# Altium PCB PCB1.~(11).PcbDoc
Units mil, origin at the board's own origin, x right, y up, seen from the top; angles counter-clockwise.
Board outline 2756 x 2756 mil, 4 copper layers (Top Layer, Internal Plane 1, Internal Plane 2, Bottom Layer), stack 18.2 mil thick; 11 components, 12 nets, 54 pads, 0 vias.
Unrouted connection lines stored in the file: 1.
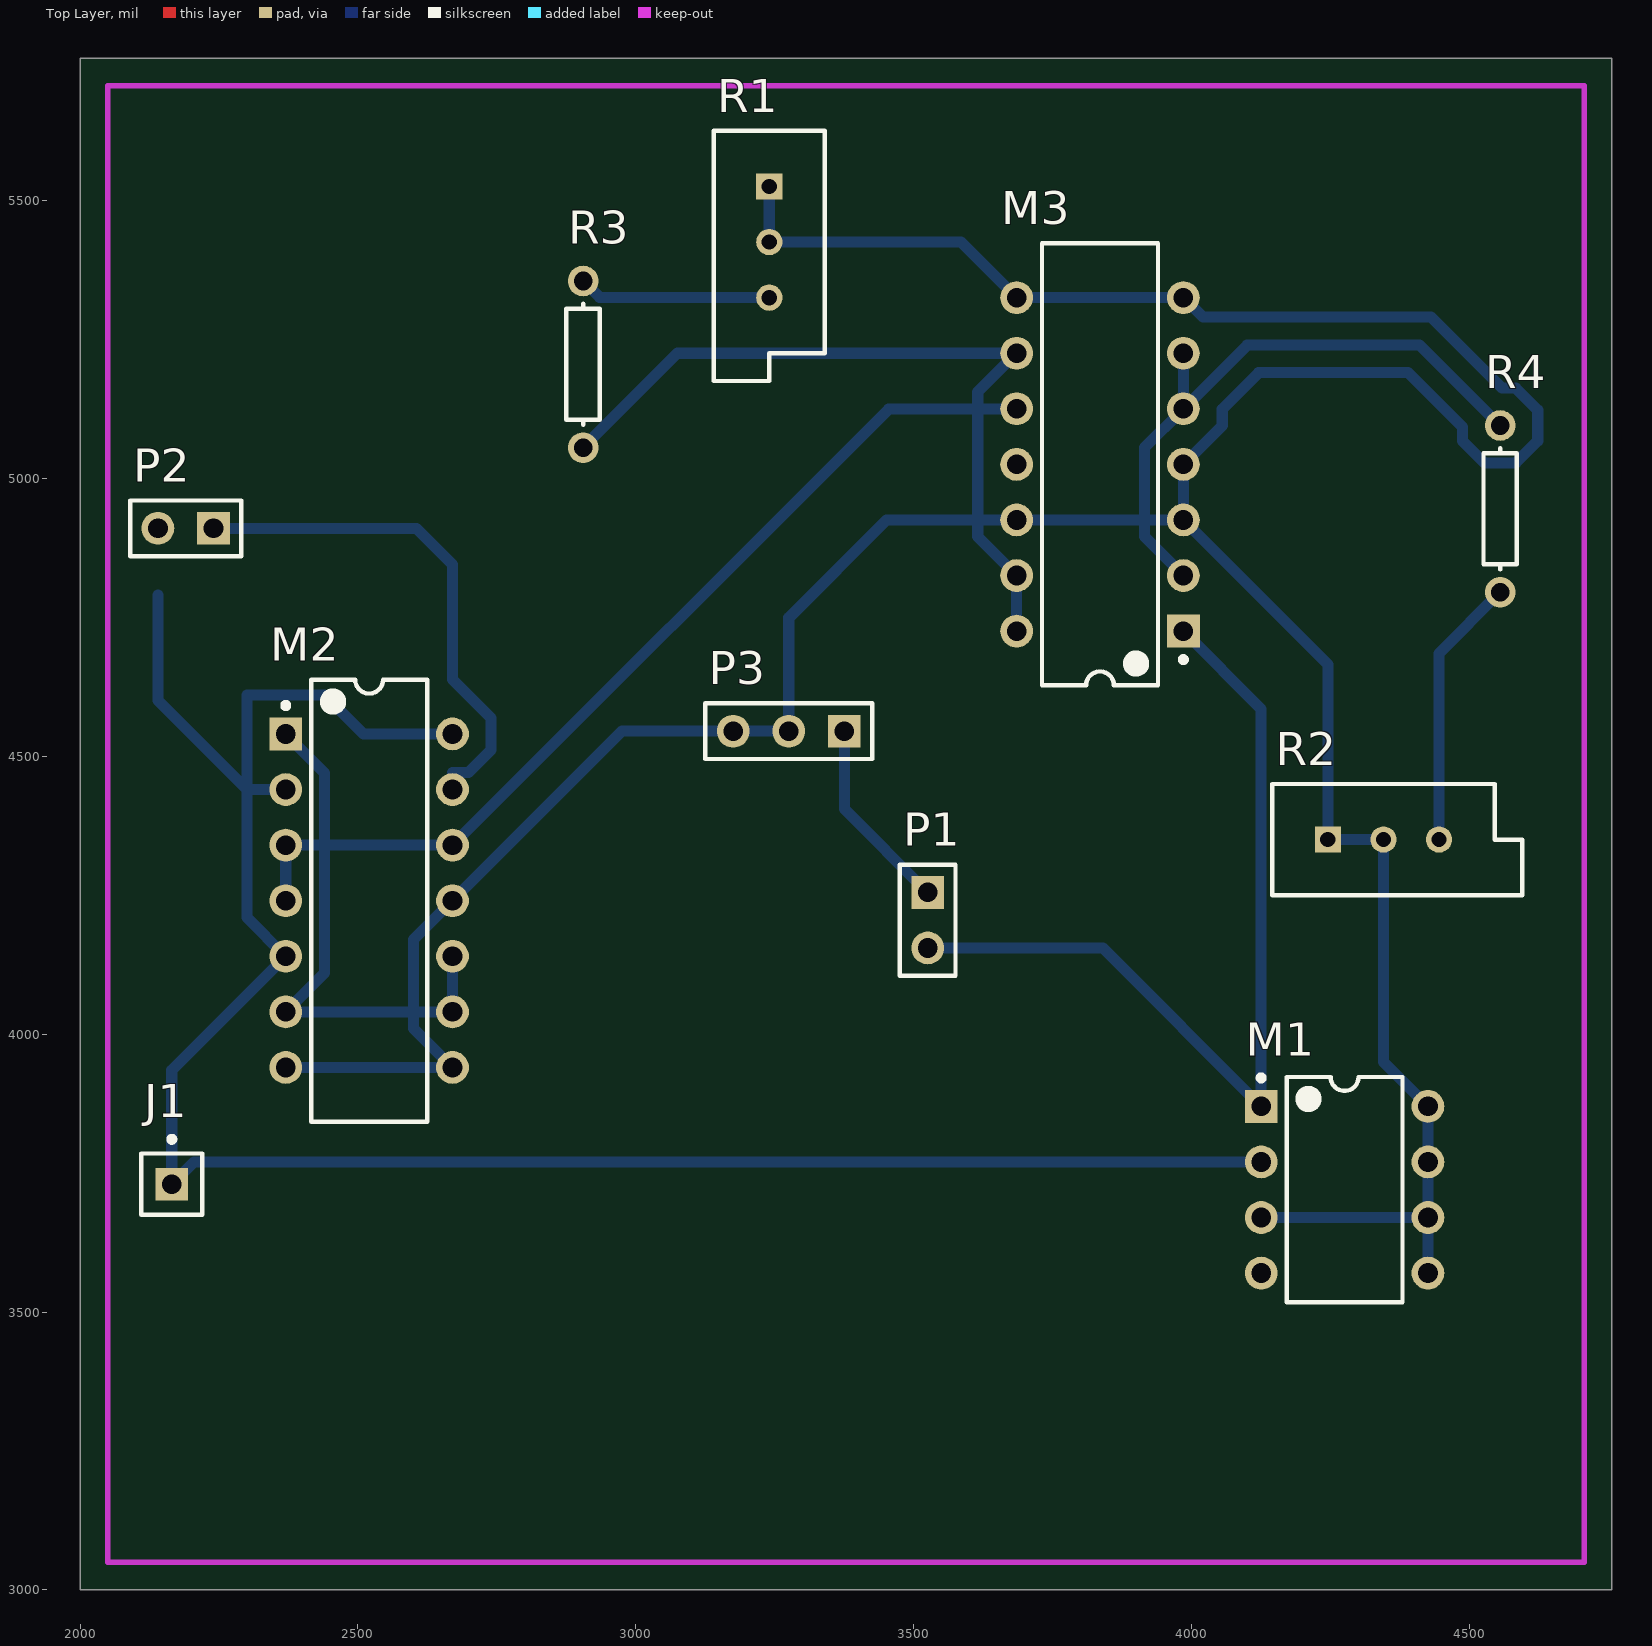
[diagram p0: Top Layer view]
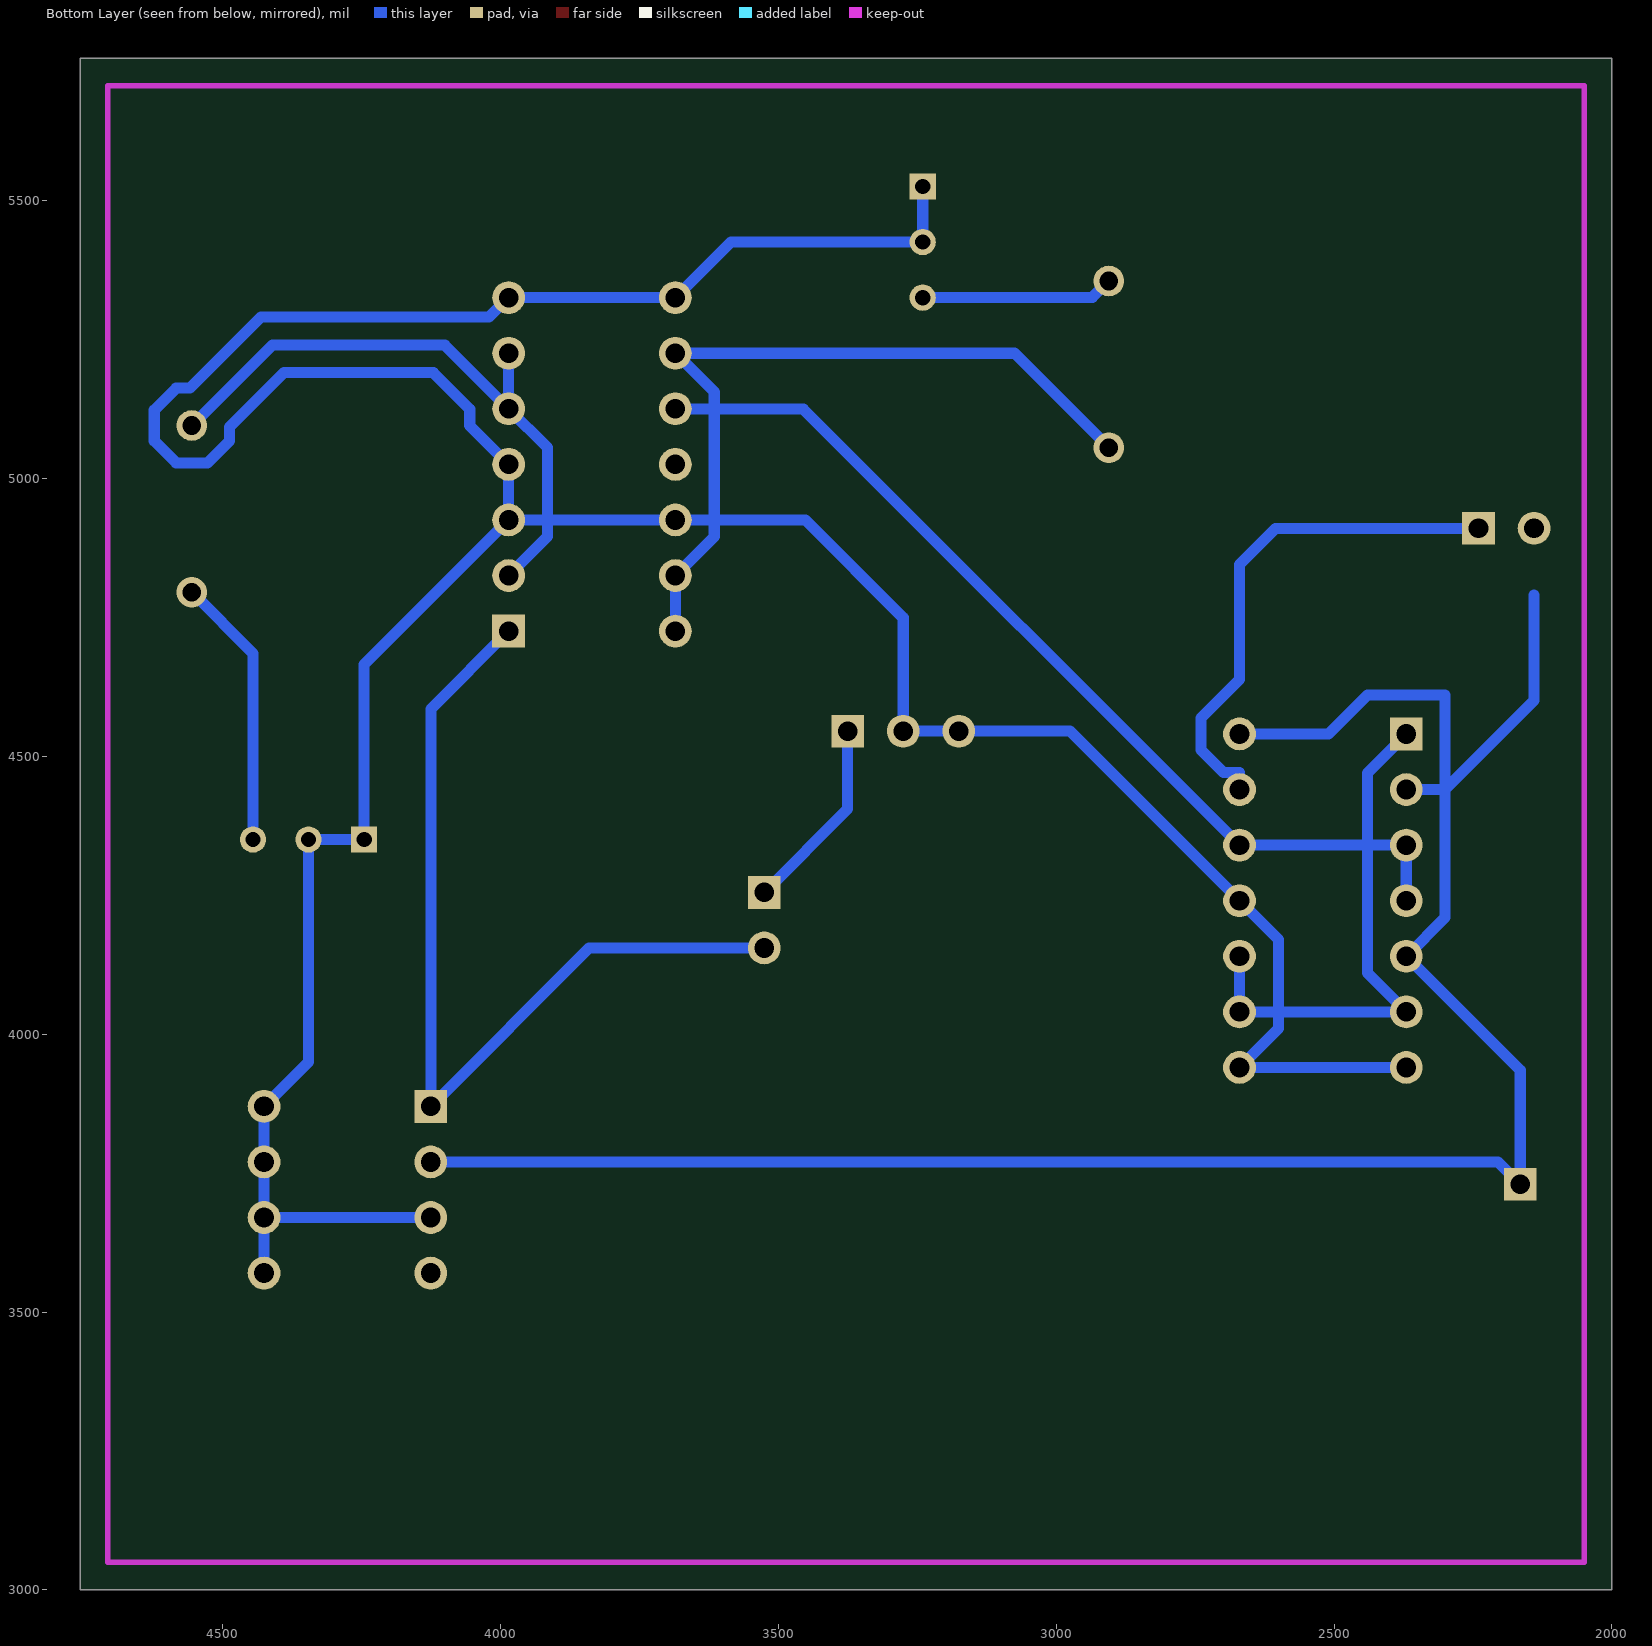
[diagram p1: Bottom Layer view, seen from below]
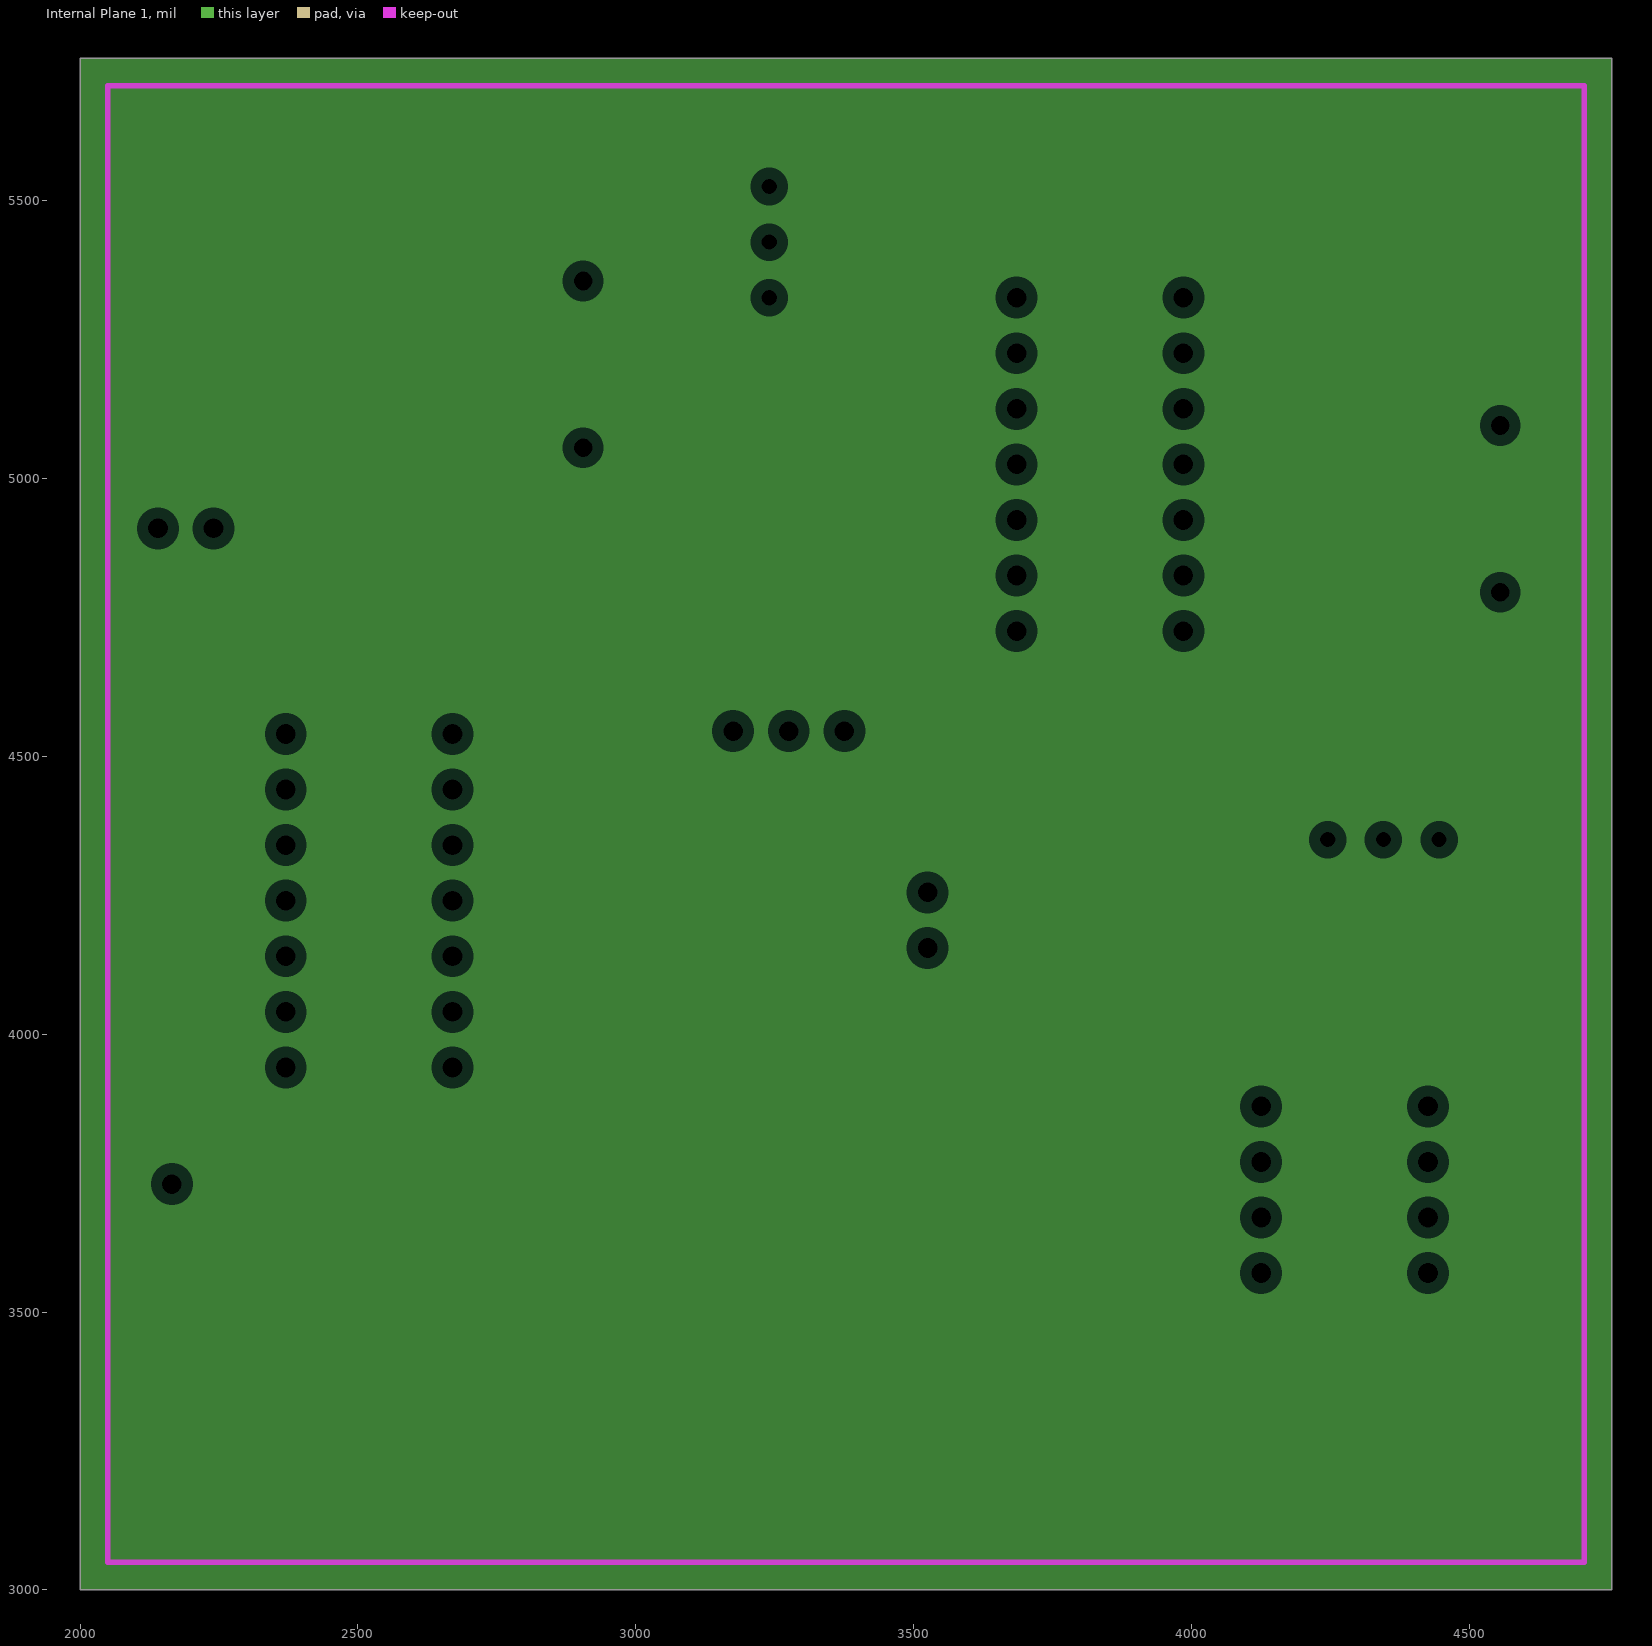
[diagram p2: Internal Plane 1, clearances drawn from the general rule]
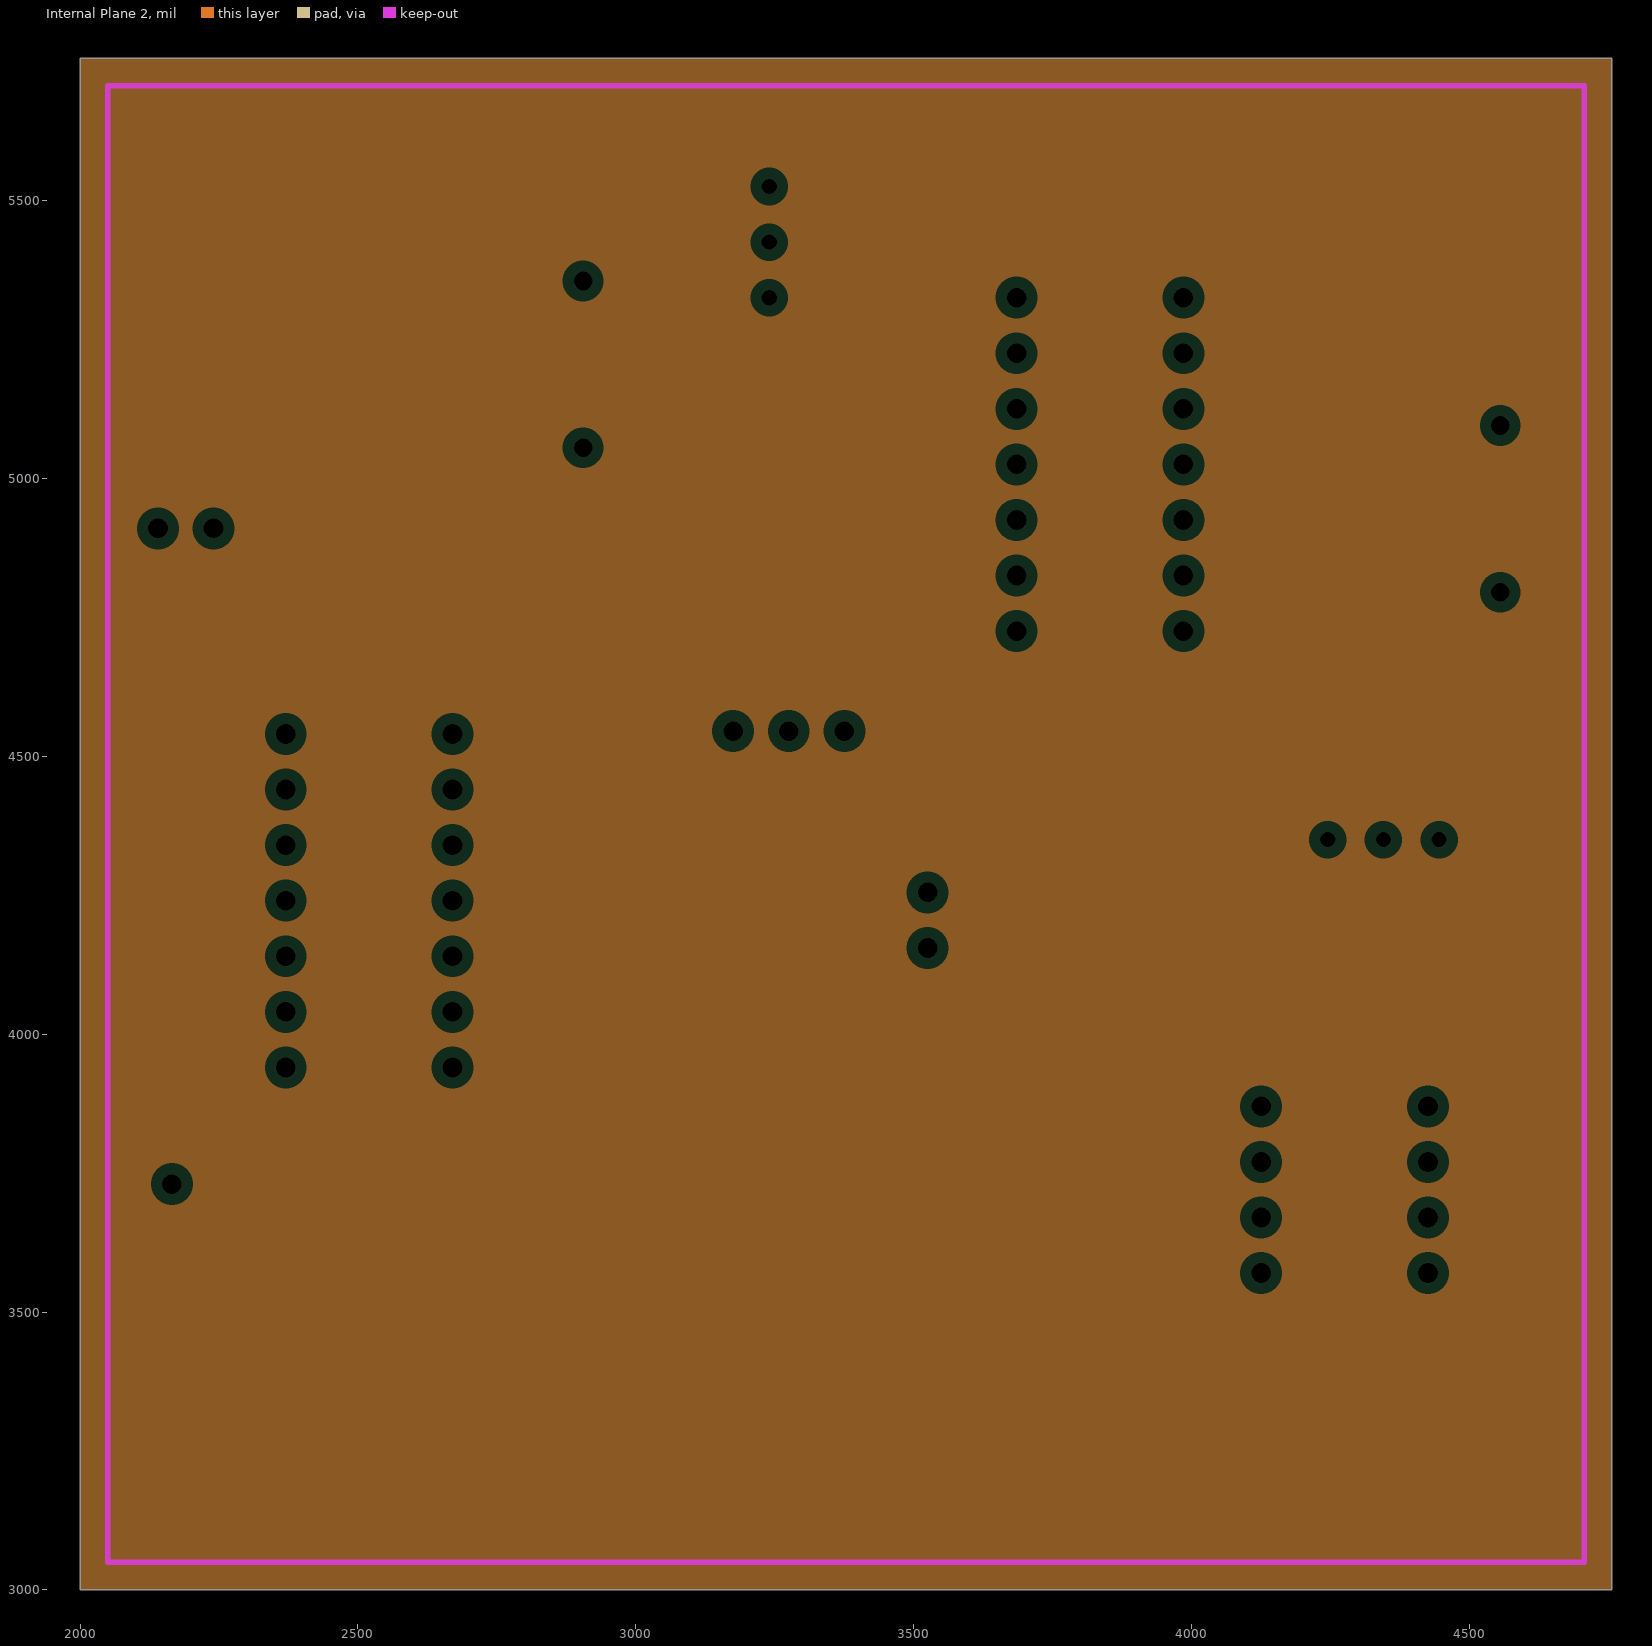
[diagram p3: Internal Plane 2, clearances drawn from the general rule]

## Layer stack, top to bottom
Top Solder: solder mask 0.4, Solder Resist, Dk 3.5
Top Layer: signal copper 1.4
Internal Plane 1: plane copper 1.4
Internal Plane 2: plane copper 1.4
Dielectric 1: dielectric 12.6, FR-4, Dk 4.8
Bottom Layer: signal copper 1.4
Bottom Solder: solder mask 0.4, Solder Resist, Dk 3.5

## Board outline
2000,3000 4756,3000 4756,5756 2000,5756

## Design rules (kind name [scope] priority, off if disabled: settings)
Clearance [All] p1: gap=30
PlaneClearance [All] p1: clearance=20
PlaneConnect [All] p1: planeconnectstyle=Relief reliefexpansion=20 reliefentries=4 reliefconductorwidth=10 reliefairgap=10
PolygonConnect [All] p1: connectstyle=Relief reliefconductorwidth=10 reliefentries=4 polygonreliefangle="90 Angle" airgapwidth=10
RoutingVias [All] p1: holewidth=32 width=62 viastyle="Through Hole" minholewidth=28 minwidth=50 maxholewidth=28 maxwidth=50
SolderMaskExpansion [All] p1: expansion=4
Width [All] p1: maxlimit=20 minlimit=20 preferedwidth=20
28 further rules are at their usual default settings.

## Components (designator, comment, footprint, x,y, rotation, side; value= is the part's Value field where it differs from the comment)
J1 "Socket" PIN1 2165,3730 r0 top
M1 "ALD1117" DIP-8 4275,3720 r0 top
M2 "ALD1105" DIP-14 2520,4240 r0 top
M3 "ALD1106" DIP-14 3835,5025 r180 top
P1 "Header 2" HDR1X2 3525,4255 r270 top
P2 "Header 2" HDR1X2 2240,4910 r180 top
P3 "Header 3" HDR1X3 3375,4545 r180 top
R1 "RPot" VR5 3240,5425 r270 top
R2 "RPot" VR5 4345,4350 r0 top
R3 "Res1" AXIAL-0.3 2905,5205 r90 top
R4 "Res1" AXIAL-0.3 4555,4945 r270 top

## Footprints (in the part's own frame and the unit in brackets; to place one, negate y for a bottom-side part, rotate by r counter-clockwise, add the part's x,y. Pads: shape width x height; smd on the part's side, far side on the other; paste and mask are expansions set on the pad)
AXIAL-0.3 [mm] "Axial Device, Thru-Hole; 2 Leads; 0.3 in Pin Spacing"
  round 1.4 hole 0.85: 1(-3.81,0) 2(3.81,0)
  silkscreen extent -2.77,-0.76 2.77,0.76
DIP-8 [mm] "DIP, 8-Pin, Row Spacing 7.62 mm, Pitch 2.54 mm"
  rect 1.5x1.5 hole 0.9: 1(-3.81,3.81)
  round 1.5 hole 0.9: 2(-3.81,1.27) 3(-3.81,-1.27) 4(-3.81,-3.81) 5(3.81,-3.81) 6(3.81,-1.27) 7(3.81,1.27) 8(3.81,3.81)
  silkscreen extent -3.93,-5.15 2.65,5.23, body extent -3.6,-5.15 3.6,5.15, height 5.33
DIP-14 [mm] "DIP, 14-Pin, Row Spacing 7.62 mm, Pitch 2.54 mm"
  rect 1.5x1.5 hole 0.9: 1(-3.81,7.62)
  round 1.5 hole 0.9: 2(-3.81,5.08) 3(-3.81,2.54) 4(-3.81,0) 5(-3.81,-2.54) 6(-3.81,-5.08) 7(-3.81,-7.62) 8(3.81,-7.62) 9(3.81,-5.08) 10(3.81,-2.54) 11(3.81,0) 12(3.81,2.54) 13(3.81,5.08) 14(3.81,7.62)
  silkscreen extent -3.93,-10.1 2.65,10.1, body extent -3.6,-10.1 3.6,10.1, height 5.08
HDR1X2 [mm] "Connector; Header; 2 Position"
  rect 1.5x1.5 hole 0.9: 1(0,0)
  round 1.5 hole 0.9: 2(2.54,0)
  silkscreen extent -1.27,-1.27 3.81,1.27
HDR1X3 [mm] "Connector; Header; 3 Position"
  rect 1.5x1.5 hole 0.9: 1(0,0)
  round 1.5 hole 0.9: 2(2.54,0) 3(5.08,0)
  silkscreen extent -1.27,-1.27 6.35,1.27
PIN1 [mm] "Connector; Plug"
  rect 1.5x1.5 hole 0.9: 1(0,0)
  silkscreen extent -1.4,-1.4 1.4,2.17
VR5 [mm] "Thru-Hole; 3 Leads"
  rect 1.2x1.2 hole 0.7: 1(-2.54,0)
  round 1.2 hole 0.7: 2(0,0) 3(2.54,0)
  silkscreen extent -5.08,-2.54 6.35,2.54

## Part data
M1: "Dual P-channel matched MOSFET array"
M2: "Dual P-channel and dual N-channel matched MOSFET array"
M3: "Quad N-channel matched MOSFET array"
P1 P2: "Header, 2-Pin"
P3: "Header, 3-Pin"
R1 R2: "Potentiometer"
R3 R4: "Resistor"

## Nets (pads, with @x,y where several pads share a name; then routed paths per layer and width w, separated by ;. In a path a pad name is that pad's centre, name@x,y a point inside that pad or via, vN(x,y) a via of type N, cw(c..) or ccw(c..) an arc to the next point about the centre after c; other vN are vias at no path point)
GND: P1.1 P3.1 | length 352.1
  Bottom Layer w20: P3.1 3375,4405 P1.1
NetJ1_1: J1.1 M1.2 M2.5 M2.14 | length 3369.5
  Bottom Layer w20: M2.14 2510,4540 2440,4610 2300,4610 2300,4210 M2.5 2165,3935 J1.1 2205,3770 M1.2
NETLABEL5: M2.13 P2.1 | length 936.4
  Bottom Layer w20: P2.1 2605,4910 2670,4845 2670,4638.33 2739.53,4568.8 2739.53,4511.2 2698.8,4470.47 2670,4470.47 M2.13
NETLABEL7: M2.2 P2.2 | length 486.3
  Bottom Layer w20: 2140,4790 2140,4600 2300,4440 M2.2
NETLABEL9: M1.3 M1.5 M1.6 M1.7 M1.8 M2.7 M2.8 M2.11 M3.3 M3.4 M3.7 M3.8 M3.12 P3.2 P3.3 R1.1 R1.2 R2.1 R2.2 | length 6857
  Bottom Layer w20: M2.7 M2.8 2600,4010 2600,4170 M2.11 2975,4545 P3.3 P3.2 3275,4749 3451,4925 M3.12 M3.3 ; R1.1 R1.2 3585,5425 M3.8 M3.7 4020,5290 4430.71,5290 4558.15,5162.56 4582.98,5162.56 4622.56,5122.98 4622.56,5067.02 4582.98,5027.44 4527.02,5027.44 4487.44,5067.02 4487.44,5091.85 4389.29,5190 4120.71,5190 4055,5124.29 4055,5095 M3.4 M3.3 ; M1.3 M1.6 ; M1.5 M1.6 ; M3.3 4245,4665 R2.1 R2.2 4345,3950 M1.8 M1.7 M1.6
NetM1_1: M1.1 M3.1 P1.2 | length 1631
  Bottom Layer w20: P1.2 3840,4155 M1.1 4125,4585 M3.1
NetM2_1: M2.1 M2.6 M2.9 M2.10 | length 958
  Bottom Layer w20: M2.1 2440,4470 2440,4110 M2.6 M2.9 M2.10
NetM2_3: M2.3 M2.4 M2.12 M3.10 | length 1740.2
  Bottom Layer w20: M2.4 M2.3 M2.12 3455,5125 M3.10
NetM3_2: M3.2 M3.5 M3.6 R4.1 | length 1135.7
  Bottom Layer w20: M3.2 3915,4895 3915,5055 M3.5 ; M3.6 M3.5 ; R4.1 4410,5240 4100,5240 M3.5
NetM3_9: M3.9 M3.13 M3.14 R3.1 | length 1408.4
  Bottom Layer w20: R3.1 3075,5225 M3.9 3615,5155 3615,4895 M3.13 M3.14
NetR1_3: R1.3 R3.2 | length 347.4
  Bottom Layer w20: R3.2 2935,5325 R1.3
NetR2_3: R2.3 R4.2 | length 490.6
  Bottom Layer w20: R2.3 4445,4685 R4.2
pads on no net: M1.4 M3.11

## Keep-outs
Keep-Out Layer:
  lines w10: 2050,3050 2050,5706 4706,5706 4706,3050 2050,3050

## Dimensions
2050,3050 to 2050,5706 on Mechanical 1
2050,3050 to 4706,3050 on Mechanical 1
